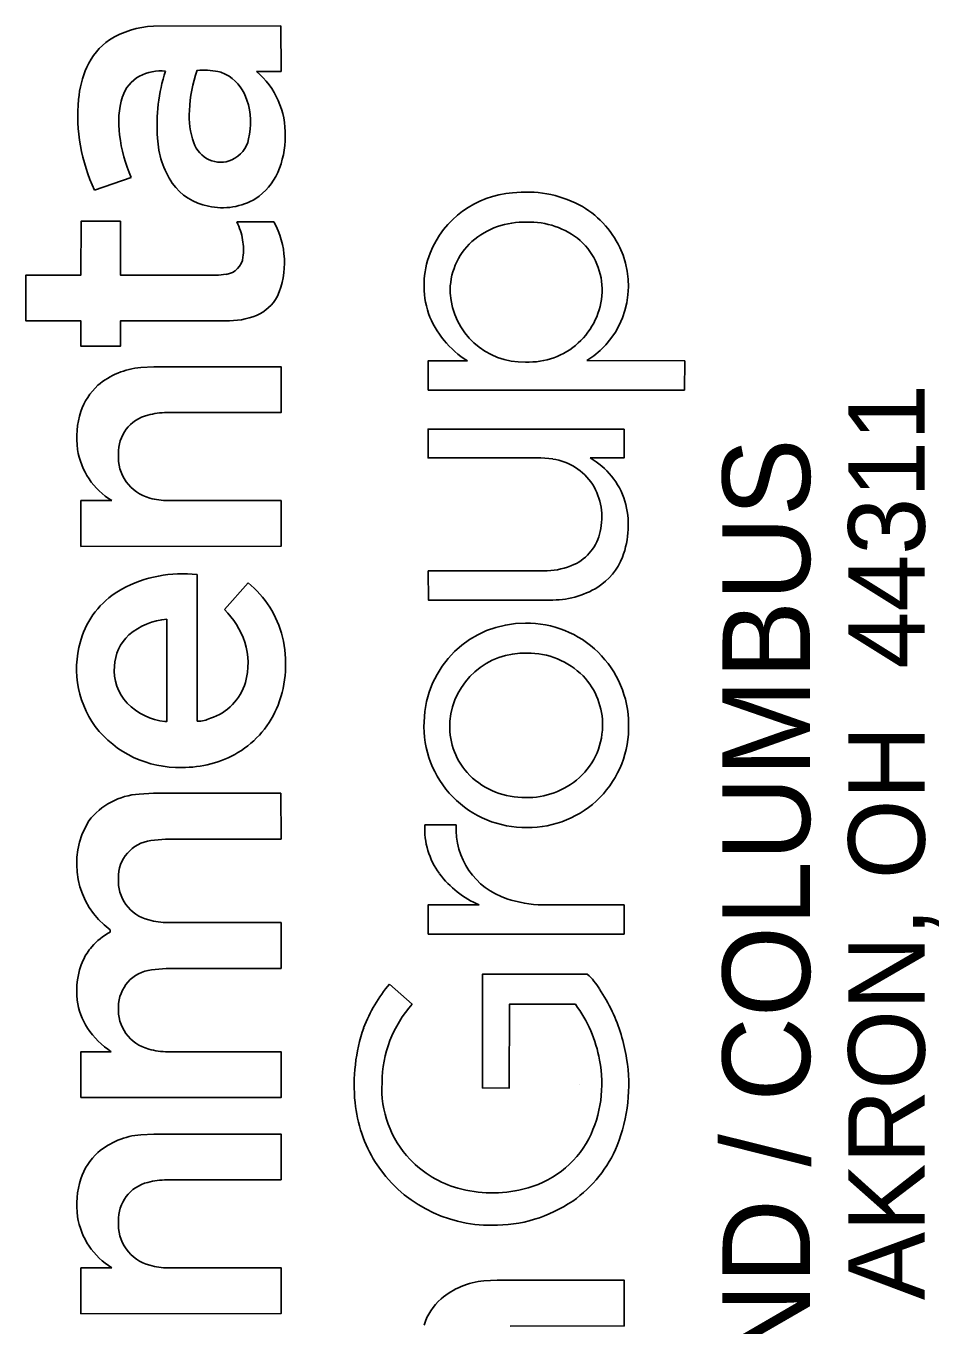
# Model space of a CAD drawing. Extents: x 0 to 1700, y 0 to 1100.
# Drawn here: x 1619.48 to 1649.21, y 167.17 to 209.46 of the extents above; entities that cross this region are included whole.
import ezdxf

# ---------------------------------------------------------------- set-up
doc = ezdxf.new("R2010")
doc.units = 0
doc.layers.add('SH_Data', color=7, linetype='Continuous')

msp = doc.modelspace()

# ---------------------------------------------------------------- linework, layer by layer
at = {"layer": 'SH_Data'}
for p, q in [((1623.633, 209.45), (1627.776, 209.459)), ((1627.776, 209.459), (1627.786, 207.978)), ((1627.786, 207.978), (1626.986, 207.978)), ((1622.909, 204.522), (1621.715, 204.116)), ((1621.271, 201.352), (1621.274, 203.104)), ((1621.274, 203.104), (1622.554, 203.104)), ((1622.554, 203.104), (1622.559, 201.352)), ((1626.348, 203.08), (1627.555, 203.08)), ((1619.482, 201.35), (1621.271, 201.352)), ((1619.482, 199.86), (1619.482, 201.35)), ((1622.559, 201.352), (1625.749, 201.352)), ((1625.749, 201.352), (1626.002, 201.375)), ((1621.271, 199.859), (1619.482, 199.86)), ((1621.271, 199.033), (1621.271, 199.859)), ((1625.984, 199.859), (1622.554, 199.858)), ((1622.554, 199.858), (1622.554, 199.033)), ((1622.554, 199.033), (1621.271, 199.033)), ((1623.219, 198.343), (1623.645, 198.366)), ((1623.645, 198.366), (1627.785, 198.366)), ((1627.785, 198.366), (1627.786, 196.877)), ((1632.576, 197.607), (1632.576, 198.557)), ((1632.576, 198.557), (1633.855, 198.557)), ((1637.746, 198.566), (1640.929, 198.554)), ((1640.929, 198.554), (1640.921, 197.607)), ((1640.921, 197.607), (1632.576, 197.607)), ((1627.786, 196.877), (1624.07, 196.873)), ((1632.576, 195.4), (1632.576, 196.336)), ((1632.576, 196.336), (1638.955, 196.332)), ((1638.955, 196.332), (1638.954, 195.398)), ((1636.245, 195.398), (1632.576, 195.4)), ((1636.64, 195.364), (1636.245, 195.398)), ((1638.954, 195.398), (1637.845, 195.398)), ((1621.271, 194.008), (1622.276, 194.01)), ((1621.271, 192.517), (1621.271, 194.008)), ((1624.111, 194.01), (1627.785, 194.01)), ((1627.785, 194.01), (1627.786, 192.522)), ((1627.786, 192.522), (1621.271, 192.517)), ((1625.054, 191.604), (1625.059, 186.829)), ((1632.577, 191.722), (1636.453, 191.725)), ((1632.583, 190.771), (1632.577, 191.722)), ((1625.941, 190.463), (1626.711, 191.331)), ((1636.537, 190.771), (1632.583, 190.771)), ((1624.072, 186.822), (1624.072, 190.148)), ((1624.008, 186.814), (1624.072, 186.822)), ((1623.165, 184.457), (1623.629, 184.484)), ((1623.629, 184.484), (1627.779, 184.484)), ((1627.779, 184.484), (1627.786, 182.991)), ((1632.466, 183.453), (1633.489, 183.453)), ((1624.029, 182.99), (1623.551, 182.941)), ((1627.786, 182.991), (1624.029, 182.99)), ((1632.576, 179.9), (1632.576, 180.85)), ((1632.576, 180.85), (1634.238, 180.85)), ((1636.302, 180.851), (1638.955, 180.848)), ((1638.955, 180.848), (1638.952, 179.9)), ((1624.109, 180.276), (1627.786, 180.274)), ((1627.786, 180.274), (1627.786, 178.784)), ((1622.222, 179.961), (1622.228, 180.036)), ((1638.952, 179.9), (1632.576, 179.9)), ((1624.045, 178.783), (1623.572, 178.737)), ((1627.786, 178.784), (1624.045, 178.783)), ((1634.34, 178.592), (1637.758, 178.596)), ((1634.34, 174.889), (1634.34, 178.592)), ((1631.318, 178.274), (1632.057, 177.621)), ((1635.224, 177.62), (1635.216, 174.888)), ((1637.368, 177.614), (1635.224, 177.62)), ((1621.271, 174.576), (1621.272, 176.069)), ((1621.272, 176.069), (1622.257, 176.069)), ((1624.103, 176.069), (1627.786, 176.068)), ((1627.786, 176.068), (1627.786, 174.578)), ((1635.216, 174.888), (1634.34, 174.889)), ((1637.5, 175), (1637.5, 175)), ((1627.786, 174.578), (1621.271, 174.576)), ((1623.219, 173.368), (1623.645, 173.391)), ((1623.645, 173.391), (1627.785, 173.391)), ((1627.785, 173.391), (1627.786, 171.902)), ((1627.786, 171.902), (1624.07, 171.898)), ((1621.271, 169.033), (1622.276, 169.036)), ((1621.271, 167.543), (1621.271, 169.033)), ((1624.111, 169.036), (1627.785, 169.036)), ((1627.785, 169.036), (1627.786, 167.548)), ((1634.392, 168.61), (1634.817, 168.633)), ((1634.817, 168.633), (1638.958, 168.633)), ((1638.958, 168.633), (1638.958, 167.144)), ((1627.786, 167.548), (1621.271, 167.543))]:
    msp.add_line(p, q, dxfattribs=at)
for points in [[(1623.633, 209.45), (1627.776, 209.459), (1627.786, 207.978)], [(1627.786, 207.978), (1626.986, 207.978)], [(1622.909, 204.522), (1621.715, 204.116)], [(1625.984, 199.859), (1622.554, 199.858), (1622.554, 199.033), (1621.271, 199.033), (1621.271, 199.859), (1619.482, 199.86), (1619.482, 201.35), (1621.271, 201.352), (1621.274, 203.104), (1622.554, 203.104), (1622.559, 201.352), (1625.749, 201.352), (1626.002, 201.375)], [(1626.348, 203.08), (1627.555, 203.08)], [(1623.219, 198.343), (1623.645, 198.366), (1627.785, 198.366), (1627.786, 196.877), (1624.07, 196.873)], [(1637.746, 198.566), (1640.929, 198.554), (1640.921, 197.607), (1632.576, 197.607)], [(1632.576, 197.607), (1632.576, 198.557), (1633.855, 198.557)], [(1636.64, 195.364), (1636.245, 195.398), (1632.576, 195.4), (1632.576, 196.336), (1638.955, 196.332), (1638.954, 195.398), (1637.845, 195.398)], [(1621.271, 192.517), (1621.271, 194.008), (1622.276, 194.01)], [(1624.111, 194.01), (1627.785, 194.01), (1627.786, 192.522), (1621.271, 192.517)], [(1625.054, 191.604), (1625.059, 186.829)], [(1636.537, 190.771), (1632.583, 190.771), (1632.577, 191.722), (1636.453, 191.725)], [(1625.941, 190.463), (1626.711, 191.331)], [(1624.008, 186.814), (1624.072, 186.822), (1624.072, 190.148)], [(1623.165, 184.457), (1623.629, 184.484), (1627.779, 184.484), (1627.786, 182.991), (1624.029, 182.99), (1623.551, 182.941)], [(1632.466, 183.453), (1633.489, 183.453)], [(1636.302, 180.851), (1638.955, 180.848), (1638.952, 179.9), (1632.576, 179.9)], [(1632.576, 179.9), (1632.576, 180.85), (1634.238, 180.85)], [(1624.109, 180.276), (1627.786, 180.274), (1627.786, 178.784), (1624.045, 178.783), (1623.572, 178.737)], [(1622.222, 179.961), (1622.228, 180.036)], [(1637.368, 177.614), (1635.224, 177.62), (1635.216, 174.888), (1634.34, 174.889), (1634.34, 178.592), (1637.758, 178.596)], [(1631.318, 178.274), (1632.057, 177.621)], [(1621.271, 174.576), (1621.272, 176.069), (1622.257, 176.069)], [(1624.103, 176.069), (1627.786, 176.068), (1627.786, 174.578), (1621.271, 174.576)], [(1623.219, 173.368), (1623.645, 173.391), (1627.785, 173.391), (1627.786, 171.902), (1624.07, 171.898)], [(1621.271, 167.543), (1621.271, 169.033), (1622.276, 169.036)], [(1624.111, 169.036), (1627.785, 169.036), (1627.786, 167.548), (1621.271, 167.543)], [(1634.392, 168.61), (1634.817, 168.633), (1638.958, 168.633), (1638.958, 167.144), (1635.242, 167.14)]]:
    msp.add_lwpolyline(points, dxfattribs=at)
for centre, radius, start, end in [((1623.726, 206.628), 2.823, 91.8942, 122.6317), ((1623.726, 206.628), 2.823, 91.8942, 122.6317), ((1623.423, 207.234), 2.151, 124.537, 155.6594), ((1623.423, 207.234), 2.151, 124.537, 155.6594), ((1624.412, 206.806), 3.228, 155.9764, 175.3149), ((1624.412, 206.806), 3.228, 155.9764, 175.3149), ((1623.763, 206.78), 1.2, 119.4252, 161.6629), ((1623.763, 206.78), 1.2, 119.4252, 161.6629), ((1623.893, 206.389), 1.607, 85.3802, 116.6222), ((1623.893, 206.389), 1.607, 85.3802, 116.6222), ((1629.394, 206.254), 5.645, 162.0821, 184.5285), ((1629.394, 206.254), 5.645, 162.0821, 184.5285), ((1629.007, 206.566), 4.205, 159.8366, 178.0362), ((1629.007, 206.566), 4.205, 159.8366, 178.0362), ((1625.255, 205.371), 2.651, 79.6696, 94.2322), ((1625.255, 205.371), 2.651, 79.6696, 94.2322), ((1625.446, 206.822), 1.192, 56.8913, 76.2149), ((1625.446, 206.822), 1.192, 56.8913, 76.2149), ((1625.26, 206.592), 1.486, 17.5984, 55.7282), ((1625.26, 206.592), 1.486, 17.5984, 55.7282), ((1625.276, 205.957), 2.647, 358.0746, 49.762), ((1625.276, 205.957), 2.647, 358.0746, 49.762), ((1626.82, 206.539), 5.65, 174.6101, 205.3899), ((1626.82, 206.539), 5.65, 174.6101, 205.3899), ((1625.379, 206.323), 2.879, 163.1369, 188.1675), ((1625.379, 206.323), 2.879, 163.1369, 188.1675), ((1624.58, 206.32), 2.217, 345.9408, 18.9919), ((1624.58, 206.32), 2.217, 345.9408, 18.9919), ((1627.328, 206.515), 2.531, 175.5903, 199.8857), ((1627.328, 206.515), 2.531, 175.5903, 199.8857), ((1627.363, 206.487), 4.867, 186.7598, 203.7981), ((1627.363, 206.487), 4.867, 186.7598, 203.7981), ((1626.639, 205.937), 2.876, 182.5676, 213.7144), ((1626.639, 205.937), 2.876, 182.5676, 213.7144), ((1625.821, 205.943), 0.92, 198.2844, 293.3081), ((1625.821, 205.943), 0.92, 198.2844, 293.3081), ((1625.76, 205.997), 0.995, 295.2883, 347.4639), ((1625.76, 205.997), 0.995, 295.2883, 347.4639), ((1625.093, 205.839), 2.828, 336.016, 0.5951), ((1625.093, 205.839), 2.828, 336.016, 0.5951), ((1625.876, 205.485), 1.969, 303.4436, 336.18), ((1625.876, 205.485), 1.969, 303.4436, 336.18), ((1625.743, 205.391), 1.828, 215.0668, 259.8133), ((1625.743, 205.391), 1.828, 215.0668, 259.8133), ((1625.877, 205.655), 2.113, 257.5256, 300.882), ((1625.877, 205.655), 2.113, 257.5256, 300.882), ((1635.54, 200.912), 3.122, 93.9866, 158.3119), ((1635.54, 200.912), 3.122, 93.9866, 158.3119), ((1635.779, 200.325), 3.729, 62.6889, 97.0135), ((1635.779, 200.325), 3.729, 62.6889, 97.0135), ((1636.062, 200.957), 3.038, 25.0657, 61.9602), ((1636.062, 200.957), 3.038, 25.0657, 61.9602), ((1624.313, 202.099), 2.259, 10.1545, 25.723), ((1624.313, 202.099), 2.259, 10.1545, 25.723), ((1625.151, 201.753), 2.746, 336.589, 28.8991), ((1625.151, 201.753), 2.746, 336.589, 28.8991), ((1635.69, 200.508), 2.567, 87.8965, 131.1812), ((1635.69, 200.508), 2.567, 87.8965, 131.1812), ((1635.875, 200.511), 2.564, 49.9089, 92.0363), ((1635.875, 200.511), 2.564, 49.9089, 92.0363), ((1624.786, 202.182), 1.778, 351.914, 10.2059), ((1624.786, 202.182), 1.778, 351.914, 10.2059), ((1635.46, 200.837), 2.169, 132.3289, 182.0949), ((1635.46, 200.837), 2.169, 132.3289, 182.0949), ((1636.077, 200.866), 2.163, 358.0487, 47.9447), ((1636.077, 200.866), 2.163, 358.0487, 47.9447), ((1636.225, 201.002), 2.871, 301.9776, 25.6418), ((1636.225, 201.002), 2.871, 301.9776, 25.6418), ((1625.919, 202.001), 0.632, 277.6142, 353.7918), ((1625.919, 202.001), 0.632, 277.6142, 353.7918), ((1635.348, 201.008), 2.907, 158.656, 198.171), ((1635.348, 201.008), 2.907, 158.656, 198.171), ((1626.456, 201.306), 1.375, 292.6889, 332.0598), ((1626.456, 201.306), 1.375, 292.6889, 332.0598), ((1635.676, 200.907), 2.388, 183.5974, 271.7045), ((1635.676, 200.907), 2.388, 183.5974, 271.7045), ((1635.859, 200.901), 2.383, 267.3149, 357.4019), ((1635.859, 200.901), 2.383, 267.3149, 357.4019), ((1626.044, 202.428), 2.569, 268.6727, 291.5235), ((1626.044, 202.428), 2.569, 268.6727, 291.5235), ((1635.515, 201.217), 3.135, 200.8399, 238.0162), ((1635.515, 201.217), 3.135, 200.8399, 238.0162), ((1623.435, 195.858), 2.494, 94.9706, 130.2248), ((1623.435, 195.858), 2.494, 94.9706, 130.2248), ((1623.174, 196.275), 2.008, 132.2238, 161.6823), ((1623.174, 196.275), 2.008, 132.2238, 161.6823), ((1623.936, 196.054), 2.801, 162.274, 187.7917), ((1623.936, 196.054), 2.801, 162.274, 187.7917), ((1623.741, 195.578), 1.249, 103.6868, 182.214), ((1623.741, 195.578), 1.249, 103.6868, 182.214), ((1624.054, 194.573), 2.3, 89.6051, 105.3303), ((1624.054, 194.573), 2.3, 89.6051, 105.3303), ((1623.513, 196.045), 2.381, 188.9646, 238.6987), ((1623.513, 196.045), 2.381, 188.9646, 238.6987), ((1623.868, 195.423), 1.378, 175.5844, 255.1382), ((1623.868, 195.423), 1.378, 175.5844, 255.1382), ((1636.355, 193.499), 1.886, 33.5008, 81.3295), ((1636.355, 193.499), 1.886, 33.5008, 81.3295), ((1636.62, 193.242), 2.48, 17.6221, 60.3897), ((1636.62, 193.242), 2.48, 17.6221, 60.3897), ((1636.207, 193.475), 2.024, 346.5618, 31.7539), ((1636.207, 193.475), 2.024, 346.5618, 31.7539), ((1624.092, 196.118), 2.107, 254.0891, 270.5284), ((1624.092, 196.118), 2.107, 254.0891, 270.5284), ((1636.172, 193.207), 2.919, 339.162, 15.6148), ((1636.172, 193.207), 2.919, 339.162, 15.6148), ((1636.685, 193.308), 1.521, 294.6321, 348.4863), ((1636.685, 193.308), 1.521, 294.6321, 348.4863), ((1636.95, 192.951), 2.101, 303.1039, 338.1561), ((1636.95, 192.951), 2.101, 303.1039, 338.1561), ((1624.588, 187.437), 4.193, 83.6212, 118.2845), ((1624.588, 187.437), 4.193, 83.6212, 118.2845), ((1636.374, 194.041), 2.317, 271.952, 294.0894), ((1636.374, 194.041), 2.317, 271.952, 294.0894), ((1623.947, 188.684), 2.791, 118.8294, 160.6224), ((1623.947, 188.684), 2.791, 118.8294, 160.6224), ((1624.7, 188.815), 3.221, 13.5328, 51.3627), ((1624.7, 188.815), 3.221, 13.5328, 51.3627), ((1636.605, 193.628), 2.857, 268.627, 301.4778), ((1636.605, 193.628), 2.857, 268.627, 301.4778), ((1624.017, 188.509), 2.743, 19.0387, 45.4432), ((1624.017, 188.509), 2.743, 19.0387, 45.4432), ((1624.22, 188.035), 2.118, 94.0131, 130.8806), ((1624.22, 188.035), 2.118, 94.0131, 130.8806), ((1635.717, 186.742), 3.276, 89.4821, 178.7775), ((1635.717, 186.742), 3.276, 89.4821, 178.7775), ((1635.791, 186.707), 3.312, 0.4227, 90.7613), ((1635.791, 186.707), 3.312, 0.4227, 90.7613), ((1624.348, 188.537), 3.219, 160.5214, 215.7815), ((1624.348, 188.537), 3.219, 160.5214, 215.7815), ((1623.851, 188.545), 1.492, 132.9855, 177.1802), ((1623.851, 188.545), 1.492, 132.9855, 177.1802), ((1624.145, 188.692), 3.79, 339.3543, 13.3771), ((1624.145, 188.692), 3.79, 339.3543, 13.3771), ((1624.362, 188.716), 2.35, 344.6072, 17.0067), ((1624.362, 188.716), 2.35, 344.6072, 17.0067), ((1635.698, 186.622), 2.423, 87.6883, 175.017), ((1635.698, 186.622), 2.423, 87.6883, 175.017), ((1635.83, 186.518), 2.526, 44.912, 90.7591), ((1635.83, 186.518), 2.526, 44.912, 90.7591), ((1623.912, 188.483), 1.557, 175.0014, 223.2876), ((1623.912, 188.483), 1.557, 175.0014, 223.2876), ((1635.978, 186.726), 2.274, 358.3228, 43.8349), ((1635.978, 186.726), 2.274, 358.3228, 43.8349), ((1624.948, 188.589), 1.752, 288.0108, 343.5536), ((1624.948, 188.589), 1.752, 288.0108, 343.5536), ((1624.273, 188.913), 2.116, 225.0645, 262.797), ((1624.273, 188.913), 2.116, 225.0645, 262.797), ((1624.774, 188.491), 3.13, 300.9439, 338.7322), ((1624.774, 188.491), 3.13, 300.9439, 338.7322), ((1625.064, 187.839), 1.01, 269.7004, 294.8729), ((1625.064, 187.839), 1.01, 269.7004, 294.8729), ((1624.454, 188.758), 3.436, 217.7434, 271.6561), ((1624.454, 188.758), 3.436, 217.7434, 271.6561), ((1635.742, 186.67), 3.303, 177.5373, 270.9452), ((1635.742, 186.67), 3.303, 177.5373, 270.9452), ((1635.542, 186.656), 2.265, 175.5147, 221.4205), ((1635.542, 186.656), 2.265, 175.5147, 221.4205), ((1635.836, 186.636), 3.268, 269.3083, 1.6791), ((1635.836, 186.636), 3.268, 269.3083, 1.6791), ((1635.966, 186.687), 2.286, 308.9038, 359.3095), ((1635.966, 186.687), 2.286, 308.9038, 359.3095), ((1624.602, 188.851), 3.528, 269.2053, 300.3357), ((1624.602, 188.851), 3.528, 269.2053, 300.3357), ((1635.699, 186.867), 2.523, 222.6626, 268.3733), ((1635.699, 186.867), 2.523, 222.6626, 268.3733), ((1635.783, 186.929), 2.589, 266.5531, 308.6725), ((1635.783, 186.929), 2.589, 266.5531, 308.6725), ((1623.319, 182.202), 2.261, 93.9112, 142.3072), ((1623.319, 182.202), 2.261, 93.9112, 142.3072), ((1623.793, 182.186), 2.66, 148.2879, 233.9556), ((1623.793, 182.186), 2.66, 148.2879, 233.9556), ((1634.939, 183.331), 2.476, 177.1621, 216.2802), ((1634.939, 183.331), 2.476, 177.1621, 216.2802), ((1635.867, 183.319), 2.382, 176.7699, 252.1504), ((1635.867, 183.319), 2.382, 176.7699, 252.1504), ((1623.692, 181.75), 1.2, 96.7576, 181.6251), ((1623.692, 181.75), 1.2, 96.7576, 181.6251), ((1635.488, 183.777), 3.183, 216.9153, 246.8862), ((1635.488, 183.777), 3.183, 216.9153, 246.8862), ((1623.788, 181.621), 1.299, 175.8157, 256.1672), ((1623.788, 181.621), 1.299, 175.8157, 256.1672), ((1636.345, 184.587), 3.736, 251.1388, 269.3469), ((1636.345, 184.587), 3.736, 251.1388, 269.3469), ((1624.085, 182.527), 2.25, 254.3463, 270.6103), ((1624.085, 182.527), 2.25, 254.3463, 270.6103), ((1623.19, 178.133), 2.068, 117.9163, 139.243), ((1623.19, 178.133), 2.068, 117.9163, 139.243), ((1623.097, 178.226), 1.937, 139.5245, 154.847), ((1623.097, 178.226), 1.937, 139.5245, 154.847), ((1623.572, 178.06), 2.439, 156.0638, 187.3493), ((1623.572, 178.06), 2.439, 156.0638, 187.3493), ((1623.711, 177.528), 1.217, 96.5532, 179.949), ((1623.711, 177.528), 1.217, 96.5532, 179.949), ((1636.249, 176.969), 2.219, 30.9891, 47.161), ((1636.249, 176.969), 2.219, 30.9891, 47.161), ((1635.081, 175.093), 4.928, 139.7948, 159.137), ((1635.081, 175.093), 4.928, 139.7948, 159.137), ((1633.546, 175.009), 5.553, 25.3031, 33.9618), ((1633.546, 175.009), 5.553, 25.3031, 33.9618), ((1623.23, 177.987), 2.091, 186.5579, 213.3885), ((1623.23, 177.987), 2.091, 186.5579, 213.3885), ((1634.95, 175.04), 3.877, 138.258, 179.7006), ((1634.95, 175.04), 3.877, 138.258, 179.7006), ((1633.944, 175.049), 4.278, 10.0751, 36.8319), ((1633.944, 175.049), 4.278, 10.0751, 36.8319), ((1623.804, 177.431), 1.314, 175.722, 255.7863), ((1623.804, 177.431), 1.314, 175.722, 255.7863), ((1633.52, 174.993), 5.583, 8.8034, 25.3348), ((1633.52, 174.993), 5.583, 8.8034, 25.3348), ((1623.943, 178.539), 2.99, 214.7043, 235.6872), ((1623.943, 178.539), 2.99, 214.7043, 235.6872), ((1635.935, 174.984), 5.768, 161.1438, 185.6281), ((1635.935, 174.984), 5.768, 161.1438, 185.6281), ((1624.097, 178.259), 2.19, 253.6672, 270.1498), ((1624.097, 178.259), 2.19, 253.6672, 270.1498), ((1634.212, 175.028), 4.018, 333.4669, 11.0367), ((1634.212, 175.028), 4.018, 333.4669, 11.0367), ((1633.782, 174.989), 5.325, 338.2887, 9.2855), ((1633.782, 174.989), 5.325, 338.2887, 9.2855), ((1634.406, 174.866), 3.338, 176.6658, 223.6912), ((1634.406, 174.866), 3.338, 176.6658, 223.6912), ((1634.668, 174.85), 4.493, 185.5077, 212.0129), ((1634.668, 174.85), 4.493, 185.5077, 212.0129), ((1623.435, 170.884), 2.494, 94.9706, 130.2248), ((1623.435, 170.884), 2.494, 94.9706, 130.2248), ((1634.934, 174.773), 3.26, 282.8815, 331.8147), ((1634.934, 174.773), 3.26, 282.8815, 331.8147), ((1634.918, 174.584), 4.12, 305.0306, 337.6757), ((1634.918, 174.584), 4.12, 305.0306, 337.6757), ((1623.174, 171.301), 2.008, 132.2238, 161.6823), ((1623.174, 171.301), 2.008, 132.2238, 161.6823), ((1634.523, 175.006), 3.519, 224.0215, 253.88), ((1634.523, 175.006), 3.519, 224.0215, 253.88), ((1634.606, 174.874), 4.454, 212.7022, 270.714), ((1634.606, 174.874), 4.454, 212.7022, 270.714), ((1623.936, 171.079), 2.801, 162.274, 187.7917), ((1623.936, 171.079), 2.801, 162.274, 187.7917), ((1623.741, 170.603), 1.249, 103.6868, 182.214), ((1623.741, 170.603), 1.249, 103.6868, 182.214), ((1624.054, 169.598), 2.3, 89.6051, 105.3303), ((1624.054, 169.598), 2.3, 89.6051, 105.3303), ((1634.659, 175.627), 4.154, 254.4535, 283.9512), ((1634.659, 175.627), 4.154, 254.4535, 283.9512), ((1634.715, 174.989), 4.569, 269.3273, 304.1963), ((1634.715, 174.989), 4.569, 269.3273, 304.1963), ((1623.513, 171.071), 2.381, 188.9646, 238.6987), ((1623.513, 171.071), 2.381, 188.9646, 238.6987), ((1623.868, 170.449), 1.378, 175.5844, 255.1382), ((1623.868, 170.449), 1.378, 175.5844, 255.1382), ((1624.092, 171.143), 2.107, 254.0891, 270.5284), ((1624.092, 171.143), 2.107, 254.0891, 270.5284), ((1634.608, 166.125), 2.494, 94.9706, 130.2248), ((1634.608, 166.125), 2.494, 94.9706, 130.2248), ((1634.347, 166.543), 2.008, 132.2238, 161.6823), ((1634.347, 166.543), 2.008, 132.2238, 161.6823)]:
    msp.add_arc(centre, radius, start, end, dxfattribs=at)

# ---------------------------------------------------------------- texts
for s, height, p in [('450 GRANT ST., AKRON, OH  44311', 2.49231, (1648.744, 141.869)), ('AKRON / CLEVELAND / COLUMBUS', 2.84845, (1645.006, 131.9))]:
    msp.add_text(s, height=height, rotation=90, dxfattribs=at).set_placement(p)

doc.saveas('drawing.dxf')
